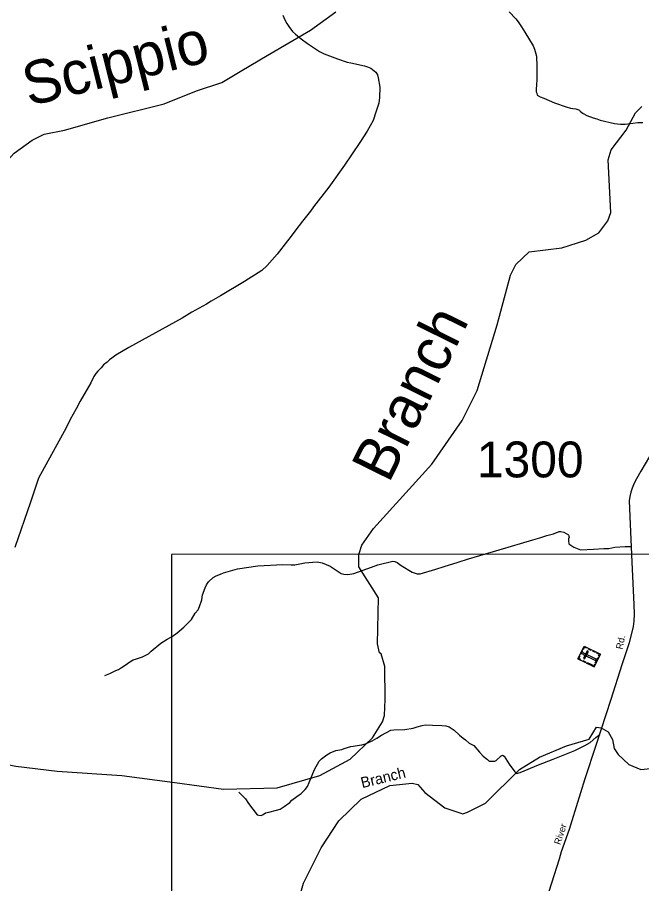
# Model space of a CAD drawing. Extents: x 2104537 to 2336408, y 34176 to 229611.
# Drawn here: x 2114749 to 2123451, y 75855 to 87935 of the extents above; entities that cross this region are included whole.
import ezdxf

# ---------------------------------------------------------------- set-up
doc = ezdxf.new("R2010")
doc.units = 0
for name, color, linetype in [('Exist Cultural Cemetery CELL', 7, 'Continuous'), ('Exist Hydrographic Creek Single Shore', 7, 'Continuous'), ('Exist Road Non-System Type 51', 7, 'Continuous'), ('Exist Road Secondary Type 51 Attributed', 7, 'Continuous'), ('Exist Road Secondary Type 51 Label', 7, 'Continuous'), ('Exist Road Secondary Type 51 Number Label', 7, 'Continuous'), ('Map Preparation Inset Cut Line', 7, 'Continuous'), ('Old_Level_32', 7, 'Continuous')]:
    doc.layers.add(name, color=color, linetype=linetype)

msp = doc.modelspace()

# ---------------------------------------------------------------- linework, layer by layer
at = {"layer": 'Exist Cultural Cemetery CELL'}
for points in [[(2122560, 78989), (2122648, 79168), (2122876, 79056), (2122789, 78877)], [(2122687, 79149), (2122682, 79139), (2122653, 79153), (2122635, 79117), (2122625, 79121), (2122648, 79168)], [(2122747, 79106), (2122708, 79126), (2122713, 79136), (2122752, 79117)], [(2122599, 78970), (2122604, 78980), (2122575, 78995), (2122593, 79031), (2122583, 79036), (2122560, 78989)], [(2122593, 79056), (2122616, 79102), (2122626, 79097), (2122603, 79051)], [(2122634, 79074), (2122626, 79057), (2122808, 78968), (2122816, 78985)], [(2122639, 78996), (2122656, 78988), (2122708, 79093), (2122691, 79102)], [(2122806, 79077), (2122768, 79096), (2122773, 79107), (2122811, 79088)], [(2122804, 78934), (2122841, 79010), (2122851, 79005), (2122814, 78929)], [(2122862, 79026), (2122851, 79031), (2122861, 79051), (2122825, 79069), (2122830, 79079), (2122876, 79056)], [(2122665, 78937), (2122627, 78957), (2122632, 78967), (2122670, 78948)], [(2122726, 78908), (2122687, 78927), (2122692, 78937), (2122731, 78918)], [(2122803, 78907), (2122793, 78912), (2122783, 78892), (2122747, 78910), (2122742, 78900), (2122788, 78877)]]:
    msp.add_lwpolyline(points, close=True, dxfattribs=at)
at = {"layer": 'Exist Hydrographic Creek Single Shore'}
for points in [[(2113215, 84345), (2114127, 85407), (2114703, 86040), (2114956, 86223), (2115125, 86307), (2115406, 86363), (2116010, 86532), (2116798, 86729), (2117248, 86912), (2117599, 87024), (2117880, 87193), (2118232, 87404), (2118836, 87756), (2119188, 88009)], [(2119868, 78198), (2119875, 78424), (2119873, 78883), (2119822, 79058), (2119797, 79075), (2119771, 79197), (2119785, 79840), (2119508, 80272), (2119508, 80446), (2119549, 80573), (2119714, 80806), (2120527, 81702), (2120949, 82311), (2121156, 82730), (2121435, 83647), (2121624, 84339), (2121698, 84488), (2121881, 84665), (2122340, 84719), (2122673, 84827), (2122855, 84929), (2122979, 85097), (2123020, 85211), (2122984, 85947), (2123025, 86087), (2123233, 86362), (2123364, 86605), (2123455, 86689)], [(2113835, 77638), (2114112, 77618), (2114729, 77494), (2115306, 77422), (2116206, 77364), (2116943, 77267), (2117621, 77172), (2118371, 77193), (2118963, 77363), (2119386, 77593), (2119700, 77887), (2119839, 78112), (2119868, 78198)], [(2118586, 75321), (2118738, 75864), (2118986, 76353), (2119231, 76730), (2119540, 77033), (2119941, 77226), (2120253, 77256), (2120333, 77238), (2120430, 77127), (2120706, 76912), (2120957, 76828), (2121023, 76853), (2121273, 76979), (2121746, 77449), (2122028, 77618), (2122403, 77778), (2122719, 77870), (2122819, 78036), (2122885, 78028), (2122985, 77970), (2123044, 77864), (2123069, 77739), (2123121, 77656), (2123270, 77515), (2123437, 77449), (2123795, 77482)]]:
    msp.add_lwpolyline(points, dxfattribs=at)
at = {"layer": 'Exist Road Non-System Type 51'}
for points in [[(2118449, 87966), (2118477, 87900), (2118504, 87850), (2118532, 87806), (2118584, 87739), (2118626, 87699), (2118705, 87633), (2118793, 87570), (2118961, 87457), (2119027, 87427), (2119212, 87354), (2119348, 87310), (2119396, 87298), (2119588, 87259), (2119630, 87245), (2119678, 87227), (2119745, 87168), (2119767, 87132), (2119779, 87092), (2119802, 86962), (2119798, 86816), (2119786, 86740), (2119747, 86610), (2119708, 86496), (2119624, 86347), (2119525, 86187), (2119308, 85872), (2119091, 85567), (2118877, 85292), (2118837, 85234), (2118724, 85093), (2118616, 84953), (2118565, 84881), (2118513, 84819), (2118371, 84634), (2118232, 84473), (2118155, 84403), (2117917, 84252), (2117580, 84050), (2117452, 83978), (2117385, 83936), (2117183, 83825), (2117045, 83738), (2116305, 83329), (2116124, 83222), (2116066, 83184), (2116032, 83158), (2116000, 83128), (2115952, 83089), (2115918, 83049), (2115869, 83003), (2115843, 82969), (2115815, 82925), (2115772, 82839), (2115627, 82584), (2115623, 82582), (2115571, 82476), (2115486, 82328), (2115430, 82209), (2115045, 81508), (2114933, 81173), (2114716, 80542)], [(2121605, 88010), (2121699, 87914), (2121731, 87874), (2121778, 87804), (2121820, 87727), (2121939, 87539), (2121957, 87493), (2121983, 87391), (2121990, 87251), (2121989, 87063), (2121979, 86933), (2121980, 86898), (2121990, 86875), (2121996, 86850), (2122038, 86828), (2122088, 86808), (2122236, 86743), (2122396, 86687), (2122459, 86667), (2122493, 86662), (2122535, 86660), (2122573, 86646), (2122597, 86622), (2122635, 86592), (2122685, 86565), (2122773, 86533), (2122827, 86519), (2122871, 86503), (2123071, 86454), (2123157, 86447), (2123219, 86445), (2123329, 86457), (2123397, 86470), (2123465, 86466)], [(2115969, 78756), (2116037, 78784), (2116121, 78826), (2116161, 78841), (2116203, 78871), (2116252, 78901), (2116316, 78947), (2116366, 78976), (2116412, 78988), (2116494, 79016), (2116532, 79038), (2116578, 79058), (2116614, 79099), (2116751, 79209), (2116839, 79264), (2116909, 79302), (2116978, 79352), (2117068, 79431), (2117176, 79539), (2117227, 79627), (2117271, 79671), (2117289, 79718), (2117319, 79814), (2117332, 79880), (2117368, 79978), (2117384, 80020), (2117414, 80062), (2117479, 80124), (2117521, 80145), (2117579, 80171), (2117625, 80187), (2117817, 80246), (2118102, 80287), (2118448, 80303), (2118566, 80299), (2118618, 80301), (2118758, 80328), (2118866, 80338), (2118930, 80341), (2119000, 80327), (2119108, 80280), (2119263, 80180), (2119301, 80170), (2119357, 80164), (2119441, 80179), (2119684, 80270), (2119774, 80300), (2119982, 80353), (2120012, 80347), (2120044, 80334), (2120100, 80292), (2120253, 80200), (2120323, 80173), (2120365, 80175), (2120584, 80240), (2120696, 80278), (2120892, 80337), (2121038, 80386), (2121463, 80508), (2121933, 80650), (2122031, 80676), (2122130, 80709), (2122222, 80735), (2122302, 80767), (2122324, 80765), (2122366, 80756), (2122432, 80718), (2122434, 80702), (2122440, 80688), (2122433, 80662), (2122431, 80642), (2122435, 80594), (2122505, 80546), (2122597, 80511), (2122777, 80517), (2122925, 80528), (2122991, 80530), (2123077, 80545), (2123221, 80555), (2123309, 80556)], [(2117836, 77132), (2117927, 77039), (2117971, 76973), (2118090, 76817), (2118113, 76809), (2118147, 76805), (2118176, 76818), (2118207, 76844), (2118253, 76852), (2118361, 76878), (2118411, 76895), (2118467, 76929), (2118545, 76987), (2118575, 77017), (2118644, 77072), (2118678, 77092), (2118704, 77112), (2118762, 77168), (2118792, 77210), (2118818, 77266), (2118893, 77449), (2118956, 77561), (2118988, 77597), (2119062, 77653), (2119108, 77680), (2119187, 77714), (2119273, 77728), (2119305, 77740), (2119399, 77767), (2119551, 77791), (2119603, 77804), (2119693, 77846), (2119761, 77882), (2119827, 77927), (2119956, 77995), (2119996, 78001), (2120150, 78004), (2120266, 78025), (2120322, 78043), (2120390, 78061), (2120434, 78069), (2120536, 78064), (2120666, 78062), (2120720, 78056), (2120768, 78043), (2120836, 77995), (2120911, 77927), (2120965, 77882), (2120997, 77860), (2121047, 77816), (2121113, 77782), (2121191, 77687), (2121242, 77635), (2121304, 77587), (2121326, 77565), (2121354, 77563), (2121402, 77565), (2121422, 77574), (2121492, 77636), (2121512, 77646), (2121534, 77634), (2121606, 77519), (2121685, 77413), (2121707, 77393), (2121759, 77403), (2122012, 77514), (2122216, 77589), (2122521, 77714), (2122659, 77781), (2122733, 77821), (2122812, 77894), (2122868, 77934)]]:
    msp.add_lwpolyline(points, dxfattribs=at)
at = {"layer": 'Exist Road Secondary Type 51 Attributed'}
msp.add_lwpolyline([(2123562, 81813), (2123439, 81608), (2123377, 81502), (2123344, 81440), (2123316, 81369), (2123299, 81313), (2123285, 81254), (2123277, 81192), (2123293, 80762), (2123314, 80336), (2123340, 79746), (2123346, 79615), (2123342, 79515), (2123330, 79439), (2123277, 79214), (2123176, 78906), (2123021, 78425), (2122814, 77782), (2122658, 77315), (2122478, 76732), (2122442, 76612), (2122329, 76298), (2122300, 76196), (2122085, 75529)], dxfattribs=at)
at = {"layer": 'Map Preparation Inset Cut Line'}
msp.add_lwpolyline([(2116896, 80446), (2116896, 37236), (2173491, 37236), (2173491, 50351), (2187500, 54766), (2187500, 55965), (2187500, 80447)], close=True, dxfattribs=at)

# ---------------------------------------------------------------- texts
at = {"layer": 'Exist Road Secondary Type 51 Label'}
for s, rotation, p in [('Rd.', 78.2488, (2123183, 79116)), ('River', 71.6942, (2122316, 76390))]:
    msp.add_text(s, height=95, rotation=rotation, dxfattribs=at).set_placement(p)
at = {"layer": 'Exist Road Secondary Type 51 Number Label'}
msp.add_text('1300', height=500, dxfattribs=at).set_placement((2121154, 81520))
at = {"layer": 'Old_Level_32'}
for s, height, rotation, p in [('Scippio', 600, 14.0406, (2114910, 86692)), ('Branch', 600, 63.7345, (2119926, 81425)), ('Branch', 150, 13.8122, (2119556, 77186))]:
    msp.add_text(s, height=height, rotation=rotation, dxfattribs=at).set_placement(p)

doc.saveas('drawing.dxf')
